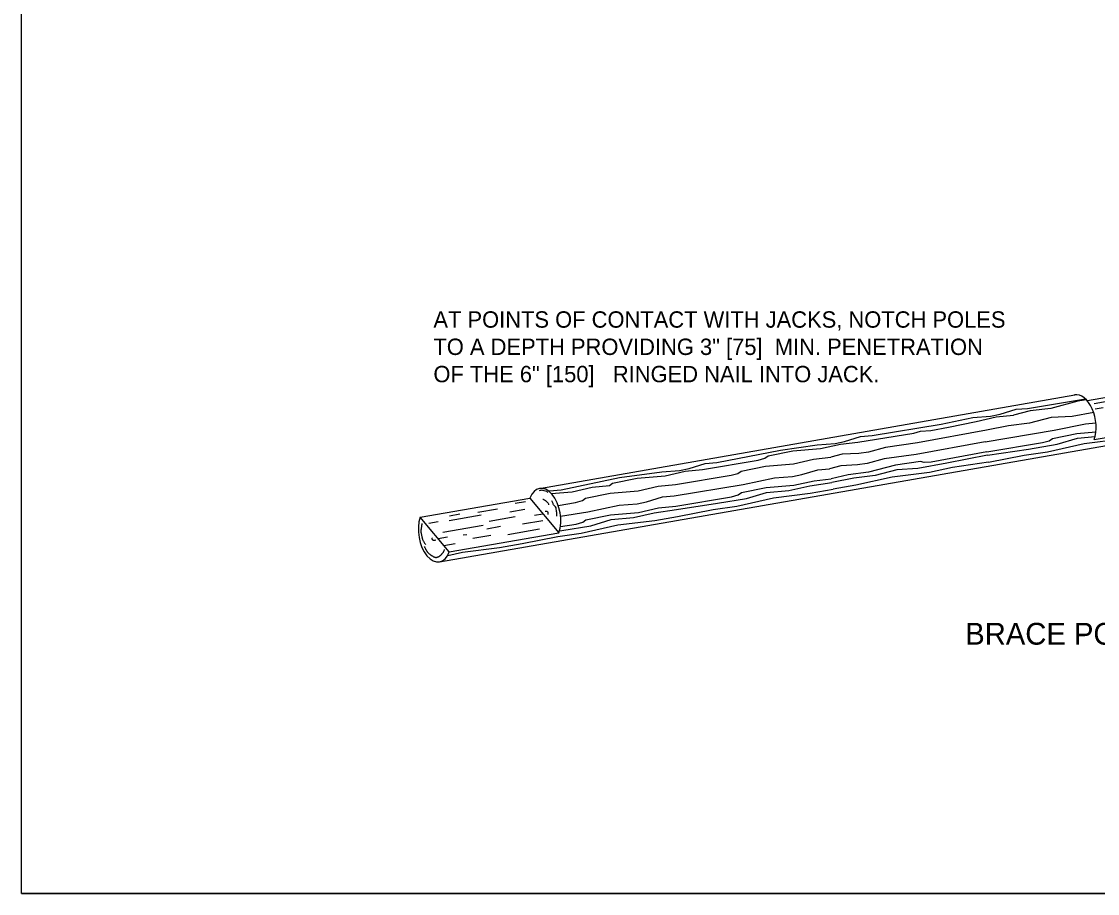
# Model space of a CAD drawing. Extents: x 49991.4 to 50021, y 49987.6 to 50011.4.
# Drawn here: x 49999.384 to 50003.324, y 49987.799 to 49990.994 of the extents above; entities that cross this region are included whole.
import ezdxf

# ---------------------------------------------------------------- set-up
doc = ezdxf.new("R2010")
doc.units = 0
for name, color, linetype in [('Level 1', 7, 'Continuous'), ('Level 2', 7, 'Continuous'), ('Level 3', 7, 'Continuous')]:
    doc.layers.add(name, color=color, linetype=linetype)

msp = doc.modelspace()

# ---------------------------------------------------------------- linework, layer by layer
at = {"layer": 'Level 1'}
for p, q in [((50000.9144, 49989.0139), (50005.951, 49989.8934)), ((50003.4416, 49989.6311), (50003.2869, 49989.6041)), ((50001.2805, 49989.2834), (50003.2413, 49989.6259)), ((50003.4436, 49989.6163), (50003.3119, 49989.5933)), ((50003.3445, 49989.5782), (50003.3151, 49989.5731)), ((50003.3119, 49989.4625), (50003.5478, 49989.5037)), ((50000.8437, 49989.1773), (50001.245, 49989.2474)), ((50001.245, 49989.2474), (50001.3514, 49989.1204)), ((50001.0541, 49989.1959), (50001.1266, 49989.2086)), ((50001.1716, 49989.1975), (50001.227, 49989.2072)), ((50001.1914, 49989.2286), (50001.2291, 49989.2353)), ((50000.95, 49989.0503), (50000.8437, 49989.1773)), ((50000.875, 49989.1561), (50000.9089, 49989.162)), ((50000.9494, 49989.1656), (50001.0674, 49989.1863)), ((50000.9513, 49989.1833), (50000.989, 49989.19)), ((50001.0961, 49989.1634), (50001.1908, 49989.1799)), ((50001.2184, 49989.1531), (50001.2923, 49989.166)), ((50001.2624, 49989.1848), (50001.2929, 49989.1902)), ((50000.9265, 49989.1227), (50001.0743, 49989.1486)), ((50000.95, 49989.0503), (50001.3514, 49989.1204)), ((50001.0879, 49989.1356), (50001.1382, 49989.1445)), ((50001.1645, 49989.1147), (50001.2802, 49989.135)), ((50000.9089, 49989.0994), (50000.9438, 49989.1055)), ((50000.9298, 49989.0744), (50000.9714, 49989.0817)), ((50001.0007, 49989.1125), (50001.0141, 49989.1148)), ((50001.0358, 49989.1006), (50001.1024, 49989.1123))]:
    msp.add_line(p, q, dxfattribs=at)
msp.add_lwpolyline([(49999.3835, 49998.9992), (50016.7501, 49998.9992), (50016.7501, 49987.7988), (49999.3835, 49987.7988)], close=True, dxfattribs=at)
for points in [[(50003.2838, 49989.6076), (50003.2516, 49989.603), (50003.1525, 49989.5764), (50003.0779, 49989.5673), (50003.0162, 49989.552)], [(50003.0681, 49989.5765), (50003.2799, 49989.6115)], [(50002.4467, 49989.4525), (50002.651, 49989.4862), (50002.6756, 49989.493), (50002.7135, 49989.4958), (50002.7782, 49989.5076), (50002.8795, 49989.5287), (50002.9527, 49989.5454), (50003.0162, 49989.552)], [(50002.4987, 49989.4772), (50002.7518, 49989.5189), (50002.8669, 49989.5429), (50002.9323, 49989.5478), (50002.967, 49989.5551), (50003.0258, 49989.5732), (50003.0681, 49989.5765)], [(50003.31, 49989.5615), (50003.2317, 49989.547), (50003.1549, 49989.5428), (50003.0748, 49989.522), (50002.9975, 49989.5125), (50002.917, 49989.4966)], [(50002.912, 49989.4545), (50003.1651, 49989.4963), (50003.2803, 49989.5203), (50003.3182, 49989.5232)], [(50001.9293, 49989.3776), (50002.1631, 49989.4236), (50002.2976, 49989.4434), (50002.3629, 49989.4484), (50002.3976, 49989.4557), (50002.4563, 49989.4738), (50002.4987, 49989.4772)], [(50002.917, 49989.4966), (50002.6647, 49989.4501), (50002.548, 49989.4337), (50002.4851, 49989.4161), (50002.4499, 49989.4114), (50002.3886, 49989.4084), (50002.3476, 49989.3972)], [(50002.9184, 49989.4175), (50003.1227, 49989.4511), (50003.1473, 49989.4579), (50003.1588, 49989.4665), (50003.2489, 49989.485), (50003.3182, 49989.4908)], [(50002.9206, 49989.4048), (50003.0707, 49989.4276), (50003.1769, 49989.445), (50003.2506, 49989.4672), (50003.3152, 49989.4731)], [(50002.925, 49989.3794), (50003.0558, 49989.4055), (50003.1413, 49989.4174), (50003.2756, 49989.4478), (50003.4108, 49989.4643), (50003.4943, 49989.4789)], [(50001.8772, 49989.353), (50002.0815, 49989.3868), (50002.1061, 49989.3936), (50002.1176, 49989.4021), (50002.2077, 49989.4205), (50002.31, 49989.4292), (50002.3833, 49989.4459), (50002.4467, 49989.4525)], [(50002.912, 49989.4545), (50002.6597, 49989.4079), (50002.5431, 49989.3915), (50002.4801, 49989.374), (50002.4449, 49989.3692), (50002.3836, 49989.3663), (50002.3426, 49989.3549)], [(50001.7782, 49989.2976), (50001.9824, 49989.3314), (50002.0071, 49989.3381), (50002.0185, 49989.3468), (50002.1087, 49989.3651), (50002.2109, 49989.3738), (50002.2842, 49989.3905), (50002.3476, 49989.3972)], [(50002.9184, 49989.4175), (50002.7149, 49989.3798), (50002.6893, 49989.3779), (50002.6758, 49989.3821), (50002.5846, 49989.3689), (50002.4856, 49989.3423), (50002.4109, 49989.3332), (50002.3491, 49989.3179)], [(50002.9206, 49989.4048), (50002.7718, 49989.3754), (50002.666, 49989.3558), (50002.5891, 49989.3516), (50002.5092, 49989.3307), (50002.4317, 49989.3213), (50002.3513, 49989.3053)], [(50001.3598, 49989.2782), (50001.5737, 49989.323), (50001.7281, 49989.3439), (50001.7935, 49989.3489), (50001.8281, 49989.3562), (50001.8868, 49989.3743), (50001.9293, 49989.3776)], [(50001.7734, 49989.2556), (50002.0263, 49989.2973), (50002.1416, 49989.3214), (50002.2069, 49989.3264), (50002.2416, 49989.3336), (50002.3003, 49989.3517), (50002.3426, 49989.3549)], [(50002.925, 49989.3794), (50002.7932, 49989.3597), (50002.7086, 49989.3417), (50002.5721, 49989.3249), (50002.4393, 49989.2946), (50002.3557, 49989.28)], [(50001.5305, 49989.2923), (50001.5368, 49989.2941), (50001.5482, 49989.3026), (50001.6383, 49989.321), (50001.7405, 49989.3297), (50001.8139, 49989.3465), (50001.8772, 49989.353)], [(50001.7798, 49989.2184), (50001.9839, 49989.252), (50002.0086, 49989.2591), (50002.0199, 49989.2677), (50002.1101, 49989.2861), (50002.2124, 49989.2946), (50002.2858, 49989.3113), (50002.3491, 49989.3179)], [(50001.3136, 49989.2737), (50001.3174, 49989.2749), (50001.3598, 49989.2782)], [(50001.3238, 49989.2644), (50001.4001, 49989.2708), (50001.4734, 49989.2877), (50001.5368, 49989.2941)], [(50001.3485, 49989.2212), (50001.4129, 49989.2319), (50001.4375, 49989.2386), (50001.449, 49989.2472), (50001.5392, 49989.2657), (50001.6414, 49989.2744), (50001.7148, 49989.2911), (50001.7782, 49989.2976)], [(50001.7819, 49989.2059), (50001.9318, 49989.2287), (50002.0381, 49989.2458), (50002.1119, 49989.2681), (50002.1941, 49989.2758), (50002.2703, 49989.293), (50002.3513, 49989.3053)], [(50001.7863, 49989.1805), (50001.917, 49989.2065), (50002.0027, 49989.2183), (50002.137, 49989.2488), (50002.2722, 49989.2654), (50002.3557, 49989.28)], [(50001.3575, 49989.1814), (50001.457, 49989.1979), (50001.5723, 49989.222), (50001.6376, 49989.2268), (50001.6723, 49989.2343), (50001.731, 49989.2522), (50001.7734, 49989.2556)], [(50001.3537, 49989.1278), (50001.3626, 49989.1291), (50001.4688, 49989.1465), (50001.5426, 49989.1687), (50001.6247, 49989.1764), (50001.7009, 49989.1935), (50001.7819, 49989.2059)], [(50001.3569, 49989.1432), (50001.4146, 49989.1527), (50001.4392, 49989.1596), (50001.4507, 49989.1681), (50001.5408, 49989.1865), (50001.6431, 49989.1952), (50001.7164, 49989.2119), (50001.7798, 49989.2184)], [(50001.217, 49989.0812), (50001.3478, 49989.107), (50001.4334, 49989.1188), (50001.5676, 49989.1495), (50001.7027, 49989.1659), (50001.7863, 49989.1805)], [(50000.9442, 49989.0377), (50000.9983, 49989.05), (50001.1336, 49989.0665), (50001.217, 49989.0812)]]:
    msp.add_lwpolyline(points, dxfattribs=at)
for centre, start_param, end_param in [((50003.2587, 49989.526), 3.925708, 6.306126), ((50001.2981, 49989.1835), 3.931522, 7.06353), ((50000.8969, 49989.1138), 0.785888, 3.92598)]:
    msp.add_ellipse(centre, major_axis=(-0.0175, 0.0999), ratio=0.577493, start_param=start_param, end_param=end_param, dxfattribs=at)
for points in [[(50001.3108, 49989.2681), (50001.3075, 49989.2714), (50001.2979, 49989.2745), (50001.2925, 49989.2761), (50001.2857, 49989.276), (50001.2794, 49989.2749)], [(50001.2932, 49989.2438), (50001.2949, 49989.2431), (50001.3026, 49989.2395), (50001.3079, 49989.2341), (50001.3124, 49989.2295), (50001.3139, 49989.2234)], [(50001.3444, 49989.1821), (50001.3443, 49989.1823), (50001.3437, 49989.1954), (50001.3425, 49989.2022), (50001.3412, 49989.2121), (50001.3323, 49989.2235), (50001.3281, 49989.2332), (50001.3257, 49989.2374)], [(50001.3008, 49989.1993), (50001.3012, 49989.1995), (50001.3013, 49989.1997), (50001.3014, 49989.1997), (50001.3015, 49989.1998), (50001.3017, 49989.2), (50001.302, 49989.2001), (50001.3025, 49989.2003), (50001.3036, 49989.2004), (50001.3048, 49989.2002), (50001.3054, 49989.2001), (50001.3059, 49989.2), (50001.3063, 49989.1999), (50001.3066, 49989.1998), (50001.3073, 49989.1995), (50001.308, 49989.1992), (50001.3084, 49989.199), (50001.3085, 49989.1988), (50001.3087, 49989.1987), (50001.3091, 49989.1983), (50001.3095, 49989.1979), (50001.3101, 49989.197), (50001.3105, 49989.1961), (50001.3106, 49989.1956), (50001.3107, 49989.1951), (50001.3108, 49989.1939), (50001.3108, 49989.1927), (50001.3108, 49989.1915), (50001.3107, 49989.1904), (50001.3107, 49989.1896), (50001.3107, 49989.1889), (50001.3106, 49989.1882), (50001.3106, 49989.1875)], [(50000.849, 49989.1544), (50000.849, 49989.1507), (50000.8489, 49989.1489), (50000.8487, 49989.147), (50000.848, 49989.1413), (50000.8472, 49989.1356), (50000.8467, 49989.1331), (50000.8461, 49989.1306), (50000.8455, 49989.1281), (50000.8454, 49989.1268), (50000.8453, 49989.1262), (50000.8453, 49989.1256), (50000.8456, 49989.1233), (50000.8462, 49989.1211), (50000.8469, 49989.1189), (50000.8473, 49989.1178), (50000.8475, 49989.1167), (50000.8483, 49989.1125), (50000.849, 49989.1084), (50000.8504, 49989.102), (50000.8512, 49989.0989), (50000.8516, 49989.0973), (50000.8521, 49989.0957), (50000.8539, 49989.0916), (50000.8563, 49989.0878), (50000.8633, 49989.0775)], [(50000.8997, 49989.0941), (50000.8994, 49989.0938), (50000.8993, 49989.0936), (50000.8993, 49989.0935), (50000.8992, 49989.0934), (50000.899, 49989.0932), (50000.8989, 49989.093), (50000.8984, 49989.0926), (50000.8974, 49989.0922), (50000.8962, 49989.092), (50000.8956, 49989.0919), (50000.8951, 49989.0918), (50000.8947, 49989.0918), (50000.8943, 49989.0918), (50000.8936, 49989.0918), (50000.8928, 49989.0919), (50000.8924, 49989.092), (50000.8922, 49989.0921), (50000.892, 49989.0922), (50000.8915, 49989.0924), (50000.891, 49989.0927), (50000.8902, 49989.0933), (50000.8895, 49989.094), (50000.8892, 49989.0944), (50000.889, 49989.0949), (50000.8885, 49989.096), (50000.8881, 49989.0971), (50000.8878, 49989.0982), (50000.8874, 49989.0994), (50000.8872, 49989.1001), (50000.887, 49989.1008), (50000.8868, 49989.1015), (50000.8866, 49989.1022)], [(50000.8586, 49989.0709), (50000.8626, 49989.0621), (50000.8635, 49989.0604), (50000.8644, 49989.0586), (50000.8654, 49989.0569), (50000.8664, 49989.0552), (50000.8678, 49989.053), (50000.8693, 49989.0508), (50000.871, 49989.0488), (50000.8719, 49989.0478), (50000.8728, 49989.0469), (50000.8765, 49989.0437), (50000.8805, 49989.0407), (50000.8829, 49989.0389), (50000.8855, 49989.0372), (50000.888, 49989.0356), (50000.8906, 49989.034), (50000.8922, 49989.0331), (50000.8938, 49989.0324), (50000.8954, 49989.0317), (50000.8963, 49989.0314), (50000.8972, 49989.0311), (50000.8988, 49989.0307), (50000.9003, 49989.0305), (50000.9018, 49989.0305), (50000.9025, 49989.0305), (50000.9033, 49989.0306), (50000.9053, 49989.031), (50000.9072, 49989.0316), (50000.9101, 49989.0328), (50000.911, 49989.0333), (50000.9127, 49989.0342), (50000.9144, 49989.0352), (50000.9175, 49989.0375), (50000.9188, 49989.0387), (50000.92, 49989.0399), (50000.9225, 49989.0424), (50000.9235, 49989.0435), (50000.9246, 49989.0446), (50000.9266, 49989.0468), (50000.9285, 49989.0491), (50000.9298, 49989.0517), (50000.9314, 49989.0557), (50000.9328, 49989.0597)]]:
    msp.add_spline(points, degree=3, dxfattribs=at)
at = {"layer": 'Level 3'}
msp.add_line((49999.3835, 49987.7988), (50016.7501, 49987.7988), dxfattribs=at)

# ---------------------------------------------------------------- texts
at = {"layer": 'Level 2'}
for s, height, p in [('AT POINTS OF CONTACT WITH JACKS, NOTCH POLES', 0.06, (50000.8919, 49989.8722)), ('TO A DEPTH PROVIDING 3" [75]  MIN. PENETRATION', 0.06, (50000.8919, 49989.7722)), ('OF THE 6" [150]   RINGED NAIL INTO JACK.', 0.06, (50000.8919, 49989.6722)), ('BRACE POLE NOTCHING', 0.08, (50002.8396, 49988.7106))]:
    msp.add_text(s, height=height, dxfattribs=at).set_placement(p)

doc.saveas('drawing.dxf')
